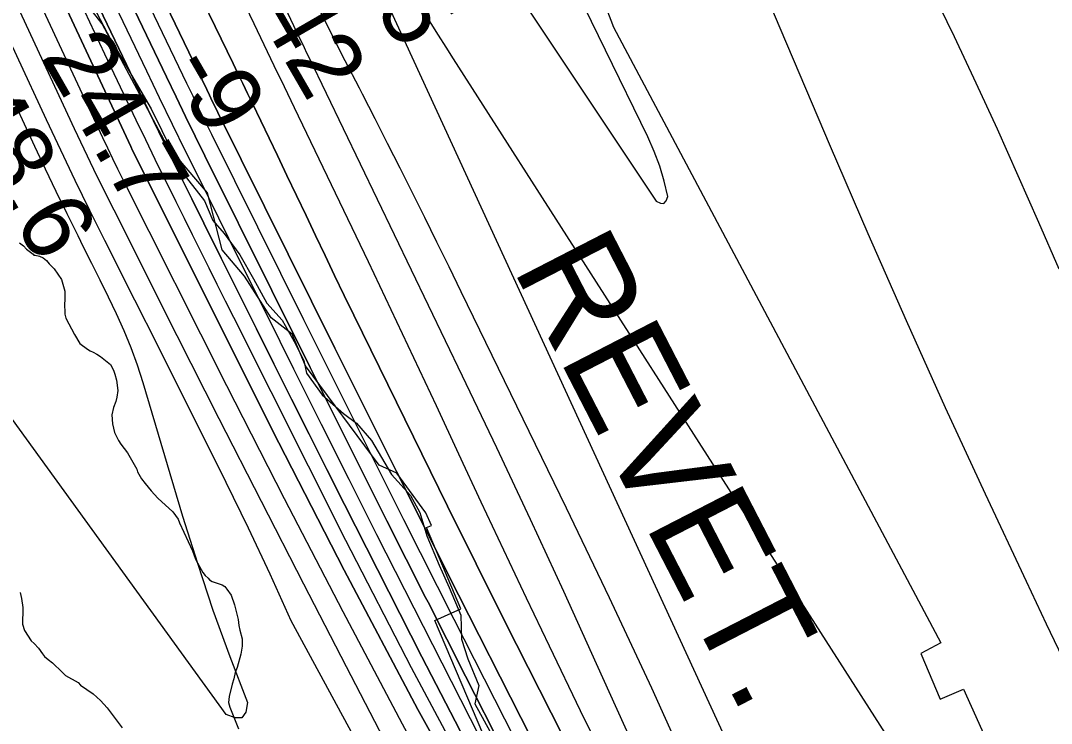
# Model space of a CAD drawing. Extents: x 3172231 to 3210228, y 940198 to 965780.
# Drawn here: x 3188879 to 3189862, y 950131 to 950801 of the extents above; entities that cross this region are included whole.
import ezdxf

# ---------------------------------------------------------------- set-up
doc = ezdxf.new("R2010")
doc.units = 0
for name, color, linetype in [('V-RIVR-EDGE', 7, 'Continuous'), ('V-RIVR-RANG', 7, 'Continuous'), ('V-RRAP-RVMT', 7, 'Continuous'), ('V-RRAP-RVMT-IDEN', 7, 'Continuous'), ('V-SITE-VEGE', 7, 'Continuous'), ('V-TOPO-DPTH', 7, 'Continuous'), ('V-TOPO-MAJR', 7, 'Continuous'), ('V-TOPO-MINR', 7, 'Continuous'), ('V-TOPO-WATR', 7, 'Continuous'), ('V-WETL-SWMP', 7, 'Continuous')]:
    doc.layers.add(name, color=color, linetype=linetype)

msp = doc.modelspace()

# ---------------------------------------------------------------- linework, layer by layer
at = {"layer": 'V-RIVR-EDGE'}
for points in [[(3188945.336, 950821.18), (3188964.95, 950783.273), (3189003.683, 950716.793), (3189034.13, 950655.52), (3189054.809, 950629.019), (3189062.542, 950610.33), (3189073.403, 950597.856), (3189088.393, 950577.593), (3189101.302, 950554.741), (3189114.209, 950531.371), (3189128.691, 950515.258), (3189140.051, 950495.004), (3189149.341, 950476.829), (3189151.904, 950464.894), (3189166.893, 950444.112), (3189187.076, 950426.429), (3189199.499, 950417.063), (3189213.98, 950400.432), (3189233.089, 950368.23), (3189251.191, 950347.959), (3189259.968, 950331.86)], [(3189259.968, 950331.86), (3189266.655, 950309.543), (3189278.514, 950281.508), (3189287.796, 950260.221), (3189299.14, 950233.743), (3189299.603, 950210.923), (3189305.78, 950192.237), (3189316.089, 950166.799), (3189312.415, 950149.175), (3189335.649, 950107.109)]]:
    msp.add_lwpolyline(points, dxfattribs=at)
at = {"layer": 'V-RRAP-RVMT'}
for p, q in [((3189424.25, 950848.074), (3189444.632, 950794.708)), ((3188956.97, 950798.104), (3188935.601, 950825.547)), ((3189018.656, 950682.166), (3188956.97, 950798.104)), ((3189444.632, 950794.708), (3189756.608, 950207.568)), ((3189057.497, 950636.766), (3189018.656, 950682.166)), ((3189071.655, 950582.509), (3189057.497, 950636.766)), ((3189092.785, 950557.428), (3189071.655, 950582.509)), ((3189118.229, 950517.465), (3189092.785, 950557.428)), ((3189138.102, 950501.884), (3189118.229, 950517.465)), ((3189151.029, 950471.695), (3189138.102, 950501.884)), ((3189221.304, 950377.065), (3189151.029, 950471.695)), ((3189238.03, 950369.299), (3189221.304, 950377.065)), ((3189265.538, 950331.649), (3189238.03, 950369.299)), ((3189271.052, 950319.426), (3189265.538, 950331.649)), ((3189266.313, 950317.508), (3189271.052, 950319.426)), ((3189298.92, 950240.018), (3189266.313, 950317.508)), ((3189274.11, 950228.885), (3189298.92, 950240.018)), ((3189329.307, 950099.555), (3189274.11, 950228.885)), ((3189756.608, 950207.568), (3189737.635, 950197.294)), ((3189737.635, 950197.294), (3189755.918, 950153.898)), ((3189755.918, 950153.898), (3189778.126, 950163.185)), ((3189778.126, 950163.185), (3189833.914, 950040.26))]:
    msp.add_line(p, q, dxfattribs=at)
at = {"layer": 'V-SITE-VEGE'}
for p, q in [((3188878.321, 950588.931), (3188882.073, 950586.068)), ((3188882.073, 950586.068), (3188884.999, 950583.197)), ((3188884.999, 950583.197), (3188891.256, 950578.286)), ((3188891.256, 950578.286), (3188892.091, 950577.467)), ((3188892.091, 950577.467), (3188893.332, 950577.477)), ((3188893.332, 950577.477), (3188897.486, 950576.275)), ((3188897.486, 950576.275), (3188900.814, 950574.651)), ((3188900.814, 950574.651), (3188904.15, 950572.195)), ((3188904.15, 950572.195), (3188906.663, 950568.906)), ((3188906.663, 950568.906), (3188911.261, 950564.396)), ((3188911.261, 950564.396), (3188918.396, 950554.111)), ((3188918.396, 950554.111), (3188921.396, 950542.96)), ((3188921.396, 950542.96), (3188921.478, 950534.264)), ((3188921.478, 950534.264), (3188921.095, 950530.948)), ((3188921.095, 950530.948), (3188921.122, 950528.051)), ((3188921.122, 950528.051), (3188921.566, 950524.743)), ((3188921.566, 950524.743), (3188921.603, 950521.016)), ((3188921.603, 950521.016), (3188922.465, 950517.299)), ((3188922.465, 950517.299), (3188930.893, 950501.644)), ((3188930.893, 950501.644), (3188935.941, 950492.995)), ((3188935.941, 950492.995), (3188943.031, 950487.678)), ((3188943.031, 950487.678), (3188945.53, 950486.044)), ((3188945.53, 950486.044), (3188948.44, 950484.828)), ((3188948.44, 950484.828), (3188952.186, 950482.796)), ((3188952.186, 950482.796), (3188955.518, 950480.756)), ((3188955.518, 950480.756), (3188965.113, 950472.978)), ((3188965.113, 950472.978), (3188968.062, 950467.624)), ((3188968.062, 950467.624), (3188969.338, 950463.909)), ((3188969.338, 950463.909), (3188970.634, 950458.124)), ((3188970.634, 950458.124), (3188971.969, 950448.199)), ((3188971.969, 950448.199), (3188971.199, 950441.981)), ((3188969.995, 950437.83), (3188967.98, 950432.014)), ((3188971.199, 950441.981), (3188969.995, 950437.83)), ((3188967.98, 950432.014), (3188966.389, 950424.96)), ((3188966.389, 950424.96), (3188966.884, 950416.269)), ((3188966.884, 950416.269), (3188969.033, 950408.007)), ((3188969.033, 950408.007), (3188972.828, 950400.591)), ((3188972.828, 950400.591), (3188974.933, 950396.884)), ((3188974.933, 950396.884), (3188981.22, 950388.662)), ((3188981.22, 950388.662), (3188990.064, 950373.011)), ((3188990.064, 950373.011), (3188990.913, 950370.533)), ((3188990.913, 950370.533), (3188994.7, 950363.944)), ((3188994.7, 950363.944), (3188998.057, 950359.42)), ((3188998.057, 950359.42), (3189003.918, 950352.437)), ((3189003.918, 950352.437), (3189010.193, 950345.457)), ((3189010.193, 950345.457), (3189024.394, 950332.34)), ((3189024.394, 950332.34), (3189029.428, 950325.348)), ((3189029.428, 950325.348), (3189030.7, 950322.046)), ((3189030.7, 950322.046), (3189043.373, 950295.25)), ((3189043.373, 950295.25), (3189045.923, 950288.236)), ((3189045.923, 950288.236), (3189046.353, 950286.581)), ((3189046.353, 950286.581), (3189053.089, 950274.639)), ((3189053.089, 950274.639), (3189055.186, 950271.76)), ((3189055.186, 950271.76), (3189058.106, 950269.302)), ((3189058.106, 950269.302), (3189059.366, 950267.66)), ((3189059.366, 950267.66), (3189061.864, 950266.025)), ((3189061.864, 950266.025), (3189071.418, 950262.804)), ((3189071.418, 950262.804), (3189073.919, 950261.17)), ((3189073.919, 950261.17), (3189076.012, 950258.706)), ((3189076.012, 950258.706), (3189080.204, 950252.947)), ((3189080.204, 950252.947), (3189083.188, 950243.866)), ((3189083.188, 950243.866), (3189086.633, 950229.821)), ((3189086.633, 950229.821), (3189087.514, 950224.031)), ((3189087.514, 950224.031), (3189088.386, 950219.485)), ((3189088.386, 950219.485), (3189090.532, 950211.227)), ((3189090.532, 950211.227), (3189090.598, 950204.186)), ((3189090.598, 950204.186), (3189089.426, 950196.721)), ((3189089.426, 950196.721), (3189085.82, 950183.849)), ((3189083.792, 950179.278), (3189082.609, 950173.054)), ((3189085.82, 950183.849), (3189083.792, 950179.278)), ((3189082.609, 950173.054), (3189080.999, 950168.074)), ((3189080.999, 950168.074), (3189078.207, 950156.453)), ((3189078.207, 950156.453), (3189077.433, 950150.649)), ((3189077.433, 950150.649), (3189078.719, 950146.107)), ((3189078.719, 950146.107), (3189087.192, 950125.483))]:
    msp.add_line(p, q, dxfattribs=at)
at = {"layer": 'V-TOPO-DPTH'}
for points in [[(3189915.067, 949077.497), (3189649.664, 949474.253), (3189631.006, 949502.688), (3189612.687, 949531.337), (3189594.88, 949560.305), (3189577.413, 949589.487), (3189405.937, 949881.818), (3189331.147, 950012.33), (3189258.142, 950143.81), (3189187.815, 950276.741), (3189119.273, 950410.64), (3188985.477, 950678.67), (3188985.176, 950679.281), (3188984.292, 950681.125), (3188411.405, 951908.58)], [(3188697.535, 951480.617), (3189056.796, 950735.385), (3189059.461, 950729.88), (3189062.139, 950724.381), (3189064.836, 950718.89), (3189067.544, 950713.406), (3189179.004, 950488.696), (3189237.697, 950370.984), (3189296.716, 950253.438), (3189356.225, 950136.139), (3189416.061, 950019.004), (3189510.051, 949835.952), (3189524.807, 949807.284), (3189539.602, 949778.636), (3189554.453, 949750.017)], [(3189554.453, 949750.017), (3189539.602, 949778.636), (3189524.807, 949807.284), (3189510.051, 949835.952), (3189416.061, 950019.004), (3189356.225, 950136.139), (3189296.716, 950253.438), (3189237.697, 950370.984), (3189179.004, 950488.696), (3189067.544, 950713.406), (3189064.836, 950718.89), (3189062.139, 950724.381), (3189059.461, 950729.88), (3189056.796, 950735.385), (3188697.535, 951480.617)], [(3188972.756, 951067.083), (3189101.643, 950798.26), (3189111.251, 950778.225), (3189120.861, 950758.19), (3189130.473, 950738.156), (3189140.088, 950718.124), (3189210.567, 950571.301), (3189232.385, 950525.58), (3189254.062, 950479.792), (3189275.527, 950433.905), (3189296.852, 950387.951), (3189318.183, 950342.001), (3189339.664, 950296.121), (3189361.369, 950250.347), (3189383.224, 950204.644), (3189412.897, 950142.983), (3189450.458, 950066.898), (3189489.029, 949991.341), (3189529.112, 949916.576), (3189570.205, 949842.339), (3189684.111, 949641.364)], [(3188972.756, 951067.083), (3189101.643, 950798.26), (3189111.251, 950778.225), (3189120.861, 950758.19), (3189130.473, 950738.156), (3189140.088, 950718.124), (3189210.567, 950571.301), (3189232.385, 950525.58), (3189254.062, 950479.792), (3189275.527, 950433.905), (3189296.852, 950387.951), (3189318.183, 950342.001), (3189339.664, 950296.121), (3189361.369, 950250.347), (3189383.224, 950204.644), (3189412.897, 950142.983), (3189450.458, 950066.898), (3189489.029, 949991.341), (3189529.112, 949916.576), (3189570.205, 949842.339), (3189684.111, 949641.364)], [(3189524.875, 949755.992), (3189486.27, 949824.252), (3189448.927, 949893.211), (3189412.425, 949962.635), (3189411.746, 949963.955), (3189375.607, 950034.426), (3189339.563, 950104.944), (3189303.66, 950175.535), (3189267.852, 950246.174), (3189265.488, 950250.85), (3189228.653, 950323.906), (3189191.93, 950397.018), (3189155.377, 950470.214), (3189118.936, 950543.467), (3189055.075, 950672.215), (3189045.834, 950690.94), (3189036.643, 950709.691), (3189027.529, 950728.479), (3189018.465, 950747.291), (3188880.407, 951035.331)], [(3188880.407, 951035.331), (3189018.465, 950747.291), (3189027.529, 950728.479), (3189036.643, 950709.691), (3189045.834, 950690.94), (3189055.075, 950672.215), (3189118.936, 950543.467), (3189155.377, 950470.214), (3189191.93, 950397.018), (3189228.653, 950323.906), (3189265.488, 950250.85), (3189267.852, 950246.174), (3189303.66, 950175.535), (3189339.563, 950104.944), (3189375.607, 950034.426), (3189411.746, 949963.955), (3189412.425, 949962.635), (3189448.927, 949893.211), (3189486.27, 949824.252), (3189524.875, 949755.992)], [(3189606.263, 949582.902), (3189490.658, 949777.444), (3189430.959, 949880.267), (3189372.669, 949983.863), (3189316.491, 950088.62), (3189261.721, 950194.151), (3189188.194, 950339.408), (3189171.278, 950372.908), (3189154.406, 950406.43), (3189137.6, 950439.985), (3189120.838, 950473.562), (3189104.117, 950507.16), (3189087.407, 950540.763), (3189070.713, 950574.374), (3189054.029, 950607.99), (3189042.605, 950631.023), (3189026.841, 950662.996), (3189011.179, 950695.017), (3188995.669, 950727.113), (3188980.261, 950759.257), (3188932.04, 950860.473)], [(3188932.04, 950860.473), (3188980.261, 950759.257), (3188995.669, 950727.113), (3189011.179, 950695.017), (3189026.841, 950662.996), (3189042.605, 950631.023), (3189054.029, 950607.99), (3189070.713, 950574.374), (3189087.407, 950540.763), (3189104.117, 950507.16), (3189120.838, 950473.562), (3189137.6, 950439.985), (3189154.406, 950406.43), (3189171.278, 950372.908), (3189188.194, 950339.408), (3189261.721, 950194.151), (3189316.491, 950088.62), (3189372.669, 949983.863), (3189430.959, 949880.267), (3189490.658, 949777.444), (3189606.263, 949582.902)], [(3189036.041, 950855.261), (3189081.915, 950760.312), (3189086.55, 950750.709), (3189091.18, 950741.104), (3189095.803, 950731.495), (3189100.42, 950721.884), (3189124.178, 950672.391), (3189133.3, 950653.343), (3189142.4, 950634.285), (3189151.465, 950615.21), (3189160.508, 950596.124), (3189169.572, 950577.048), (3189178.688, 950557.998), (3189187.882, 950538.984), (3189197.127, 950519.996), (3189286.324, 950337.738), (3189340.854, 950227.973), (3189396.248, 950118.652), (3189452.939, 950009.997), (3189510.493, 949901.786), (3189645.603, 949651.359)], [(3189645.603, 949651.359), (3189510.493, 949901.786), (3189452.939, 950009.997), (3189396.248, 950118.652), (3189340.854, 950227.973), (3189286.324, 950337.738), (3189197.127, 950519.996), (3189187.882, 950538.984), (3189178.688, 950557.998), (3189169.572, 950577.048), (3189160.508, 950596.124), (3189151.465, 950615.21), (3189142.4, 950634.285), (3189133.3, 950653.343), (3189124.178, 950672.391), (3189100.42, 950721.884), (3189095.803, 950731.495), (3189091.18, 950741.104), (3189086.55, 950750.709), (3189081.915, 950760.312), (3189036.041, 950855.261)]]:
    msp.add_lwpolyline(points, dxfattribs=at)
at = {"layer": 'V-TOPO-MAJR'}
for points in [[(3189709.332, 949635.448), (3189630.467, 949772.757), (3189605.244, 949817.912), (3189580.749, 949863.448), (3189557.348, 949909.555), (3189534.675, 949956.043), (3189512.687, 950002.88), (3189490.882, 950049.802), (3189469.35, 950096.85), (3189448.001, 950143.982), (3189428.396, 950187.602), (3189397.11, 950256.481), (3189365.463, 950325.193), (3189333.275, 950393.652), (3189300.725, 950461.943), (3189154.694, 950765.236), (3189152.356, 950770.106), (3189150.026, 950774.979), (3189147.706, 950779.857), (3189145.394, 950784.739), (3188703.306, 951720.929)], [(3188818.55, 950890.161), (3188903.701, 950706.673), (3188917.3, 950677.732), (3188931.083, 950648.881), (3188945.143, 950620.163), (3188959.387, 950591.534), (3188987.934, 950534.839), (3189009.775, 950491.392), (3189031.575, 950447.925), (3189053.317, 950404.428), (3189075.02, 950360.912), (3189096.296, 950317.197), (3189117.042, 950273.239), (3189136.994, 950228.915), (3189516.871, 949527.552), (3189530.283, 949505.679), (3189543.984, 949483.993), (3189558.119, 949462.587), (3189572.544, 949441.368), (3189951.891, 948895.282)]]:
    msp.add_lwpolyline(points, dxfattribs=at)
at = {"layer": 'V-TOPO-MINR'}
for points in [[(3188411.405, 951908.58), (3188984.292, 950681.125), (3188985.176, 950679.281), (3188985.477, 950678.67), (3189119.273, 950410.64), (3189187.815, 950276.741), (3189258.142, 950143.81), (3189331.147, 950012.33), (3189405.937, 949881.818), (3189577.413, 949589.487), (3189594.88, 949560.305), (3189612.687, 949531.337), (3189631.006, 949502.688), (3189649.664, 949474.253), (3189915.067, 949077.497)], [(3188576.643, 951506.963), (3188957.402, 950689.628), (3188962.14, 950679.576), (3188966.94, 950669.554), (3188971.831, 950659.576), (3188976.783, 950649.627), (3189075.782, 950453.01), (3189130.785, 950345.04), (3189186.463, 950237.423), (3189243.152, 950130.335), (3189300.515, 950023.6), (3189504.638, 949648.049)], [(3188697.535, 951480.617), (3189056.796, 950735.385), (3189059.461, 950729.88), (3189062.139, 950724.381), (3189064.836, 950718.89), (3189067.544, 950713.406), (3189179.004, 950488.696), (3189237.697, 950370.984), (3189296.716, 950253.438), (3189356.225, 950136.139), (3189416.061, 950019.004), (3189510.051, 949835.952), (3189524.807, 949807.284), (3189539.602, 949778.636), (3189554.453, 949750.017)], [(3188793.992, 951248.138), (3189037.616, 950741.331), (3189043.487, 950729.175), (3189049.388, 950717.034), (3189055.334, 950704.916), (3189061.31, 950692.811), (3189149.078, 950515.868), (3189196.583, 950420.483), (3189244.294, 950325.201), (3189292.313, 950230.074), (3189340.538, 950135.051), (3189385.784, 950046.254), (3189411.591, 949995.733), (3189437.466, 949945.247), (3189463.442, 949894.812), (3189489.486, 949844.413), (3189492.099, 949839.37), (3189517.298, 949791.746), (3189543.047, 949744.428)], [(3188745.111, 951096.931), (3188930.535, 950698.144), (3188939.71, 950678.65), (3188949.007, 950659.215), (3188958.485, 950639.867), (3188968.084, 950620.579), (3189028.46, 950500.67), (3189068.477, 950421.542), (3189108.681, 950342.509), (3189149.164, 950263.619), (3189189.834, 950184.825), (3189221.232, 950124.258), (3189251.118, 950066.152), (3189280.753, 950007.92), (3189310.014, 949949.5), (3189339.026, 949890.953), (3189368.566, 949832.701), (3189399.059, 949774.968), (3189430.983, 949718.014)], [(3188972.756, 951067.083), (3189101.643, 950798.26), (3189111.251, 950778.225), (3189120.861, 950758.19), (3189130.473, 950738.156), (3189140.088, 950718.124), (3189210.567, 950571.301), (3189232.385, 950525.58), (3189254.062, 950479.792), (3189275.527, 950433.905), (3189296.852, 950387.951), (3189318.183, 950342.001), (3189339.664, 950296.121), (3189361.369, 950250.347), (3189383.224, 950204.644), (3189412.897, 950142.983), (3189450.458, 950066.898), (3189489.029, 949991.341), (3189529.112, 949916.576), (3189570.205, 949842.339), (3189684.111, 949641.364)], [(3188880.407, 951035.331), (3189018.465, 950747.291), (3189027.529, 950728.479), (3189036.643, 950709.691), (3189045.834, 950690.94), (3189055.075, 950672.215), (3189118.936, 950543.467), (3189155.377, 950470.214), (3189191.93, 950397.018), (3189228.653, 950323.906), (3189265.488, 950250.85), (3189267.852, 950246.174), (3189303.66, 950175.535), (3189339.563, 950104.944), (3189375.607, 950034.426), (3189411.746, 949963.955), (3189412.425, 949962.635), (3189448.927, 949893.211), (3189486.27, 949824.252), (3189524.875, 949755.992)], [(3188905.762, 950949.101), (3188999.346, 950753.267), (3189011.589, 950727.791), (3189023.907, 950702.352), (3189036.336, 950676.967), (3189048.84, 950651.619), (3189087.2, 950574.283), (3189113.395, 950521.565), (3189139.638, 950468.871), (3189165.955, 950416.213), (3189192.32, 950363.58), (3189218.774, 950310.992), (3189245.298, 950258.439), (3189271.927, 950205.939), (3189298.626, 950153.474), (3189335.889, 950080.429), (3189382.118, 949991.935), (3189429.473, 949904.062), (3189478.519, 949817.121), (3189528.691, 949730.801)], [(3189328.861, 950863.825), (3189485.415, 950628.904), (3189489.446, 950626.887), (3189492.74, 950626.666), (3189494.926, 950629.139), (3189496.373, 950633.408), (3189492.931, 950648.015), (3189488.748, 950662.374), (3189483.453, 950676.361), (3189477.419, 950690.1), (3189396.636, 950856.006)], [(3189876.677, 950184.907), (3189857.402, 950225.378), (3189838.287, 950265.925), (3189799.286, 950349.289), (3189761.244, 950431.778), (3189723.811, 950514.538), (3189687.289, 950597.705), (3189651.375, 950681.142), (3189574.642, 950862.143)], [(3189036.041, 950855.261), (3189081.915, 950760.312), (3189086.55, 950750.709), (3189091.18, 950741.104), (3189095.803, 950731.495), (3189100.42, 950721.884), (3189124.178, 950672.391), (3189133.3, 950653.343), (3189142.4, 950634.285), (3189151.465, 950615.21), (3189160.508, 950596.124), (3189169.572, 950577.048), (3189178.688, 950557.998), (3189187.882, 950538.984), (3189197.127, 950519.996), (3189286.324, 950337.738), (3189340.854, 950227.973), (3189396.248, 950118.652), (3189452.939, 950009.997), (3189510.493, 949901.786), (3189645.603, 949651.359)], [(3189869.474, 950563.91), (3189850.153, 950608.531), (3189830.495, 950653.004), (3189810.611, 950697.379), (3189790.306, 950741.559), (3189769.665, 950785.58), (3189748.518, 950829.36)], [(3188940.158, 950810.217), (3188959.316, 950769.246), (3188980.206, 950725.263), (3188989.215, 950706.418), (3188998.289, 950687.603), (3189007.459, 950668.835), (3189016.693, 950650.098), (3189019.606, 950644.225), (3189027.428, 950628.447), (3189035.245, 950612.666), (3189043.055, 950596.881), (3189050.861, 950581.094), (3189058.678, 950565.313), (3189066.515, 950549.543), (3189074.383, 950533.787), (3189082.272, 950518.042), (3189189.054, 950305.427), (3189251.621, 950184.078), (3189315.882, 950063.656), (3189382.685, 949944.626), (3189451.182, 949826.523), (3189594.41, 949585.497)], [(3189162.036, 950815.889), (3189175.217, 950789.465), (3189188.56, 950763.122), (3189202.012, 950736.834), (3189204.94, 950731.154), (3189216.961, 950707.723), (3189228.92, 950684.259), (3189240.784, 950660.747), (3189252.585, 950637.204), (3189264.303, 950613.619), (3189275.974, 950590.011), (3189287.573, 950566.367), (3189299.125, 950542.7), (3189399.463, 950336.346), (3189440.457, 950250.588), (3189480.684, 950164.477), (3189519.759, 950077.837), (3189558.066, 949990.845), (3189615.725, 949857.504), (3189624.71, 949836.955), (3189633.805, 949816.455), (3189643.065, 949796.03), (3189652.435, 949775.654), (3189662.146, 949755.448)], [(3189232.397, 950809.962), (3189738.345, 949709.462), (3189754.512, 949674.788), (3189771.491, 949640.534), (3189789.688, 949606.912), (3189808.698, 949573.71), (3189833.828, 949531.592), (3189866.632, 949478.051)], [(3189263.449, 950809.645), (3189270.464, 950798.363), (3189277.513, 950787.102), (3189284.614, 950775.874), (3189291.749, 950764.668), (3189922.693, 949778.714)], [(3188864.875, 950741.17), (3188892.655, 950681.193), (3188902.704, 950659.772), (3188912.893, 950638.418), (3188923.29, 950617.165), (3188933.827, 950595.979), (3188939.151, 950585.405), (3188947.087, 950569.535), (3188954.964, 950553.637), (3188962.755, 950537.696), (3188970.488, 950521.727), (3188977.781, 950505.583), (3188984.549, 950489.237), (3188990.528, 950472.585), (3188995.981, 950455.731), (3189033.86, 950328.328), (3189047.892, 950283.38), (3189062.73, 950238.713), (3189078.777, 950194.466), (3189095.63, 950150.499), (3189094.006, 950141.396), (3189090.399, 950135.893), (3189083.82, 950135.788), (3189075.26, 950139.281), (3188799.646, 950519.622)]]:
    msp.add_lwpolyline(points, dxfattribs=at)
at = {"layer": 'V-TOPO-WATR'}
msp.add_lwpolyline([(3188932.04, 950860.473), (3188980.261, 950759.257), (3188995.669, 950727.113), (3189011.179, 950695.017), (3189026.841, 950662.996), (3189042.605, 950631.023), (3189054.029, 950607.99), (3189070.713, 950574.374), (3189087.407, 950540.763), (3189104.117, 950507.16), (3189120.838, 950473.562), (3189137.6, 950439.985), (3189154.406, 950406.43), (3189171.278, 950372.908), (3189188.194, 950339.408), (3189261.721, 950194.151), (3189316.491, 950088.62), (3189372.669, 949983.863), (3189430.959, 949880.267), (3189490.658, 949777.444), (3189606.263, 949582.902)], dxfattribs=at)
at = {"layer": 'V-WETL-SWMP'}
msp.add_lwpolyline([(3188878.908, 950255.579), (3188880.204, 950249.794), (3188881.528, 950241.111), (3188881.589, 950234.487), (3188881.206, 950231.171), (3188881.261, 950225.375), (3188882.975, 950219.18), (3188889.278, 950209.302), (3188892.199, 950206.844), (3188896.382, 950202.329), (3188900.158, 950196.981), (3188902.252, 950194.517), (3188905.591, 950191.649), (3188909.762, 950188.376), (3188918.955, 950179.353), (3188922.295, 950176.485), (3188934.367, 950169.559), (3188936.46, 950167.094), (3188948.544, 950158.926), (3188951.887, 950155.645), (3188955.644, 950152.368), (3188961.92, 950145.387), (3188976.175, 950126.474)], dxfattribs=at)

# ---------------------------------------------------------------- texts
at = {"layer": 'V-RIVR-RANG'}
for s, rotation, p in [('-65', 300.074167, (3189176.987, 950882.638)), ('-42', 300.074167, (3189089.797, 950833.654)), ('24.7', 299.788326, (3188898.001, 950766.941)), ('-9', 300.074167, (3189019.129, 950756.136)), ('48.6', 299.788326, (3188810.423, 950718.645))]:
    msp.add_text(s, height=67, rotation=rotation, dxfattribs=at).set_placement(p)
at = {"layer": 'V-RRAP-RVMT-IDEN'}
msp.add_text('REVET.', height=99.9998, rotation=297.2661, dxfattribs=at).set_placement((3189347.683, 950565.372))

doc.saveas('drawing.dxf')
